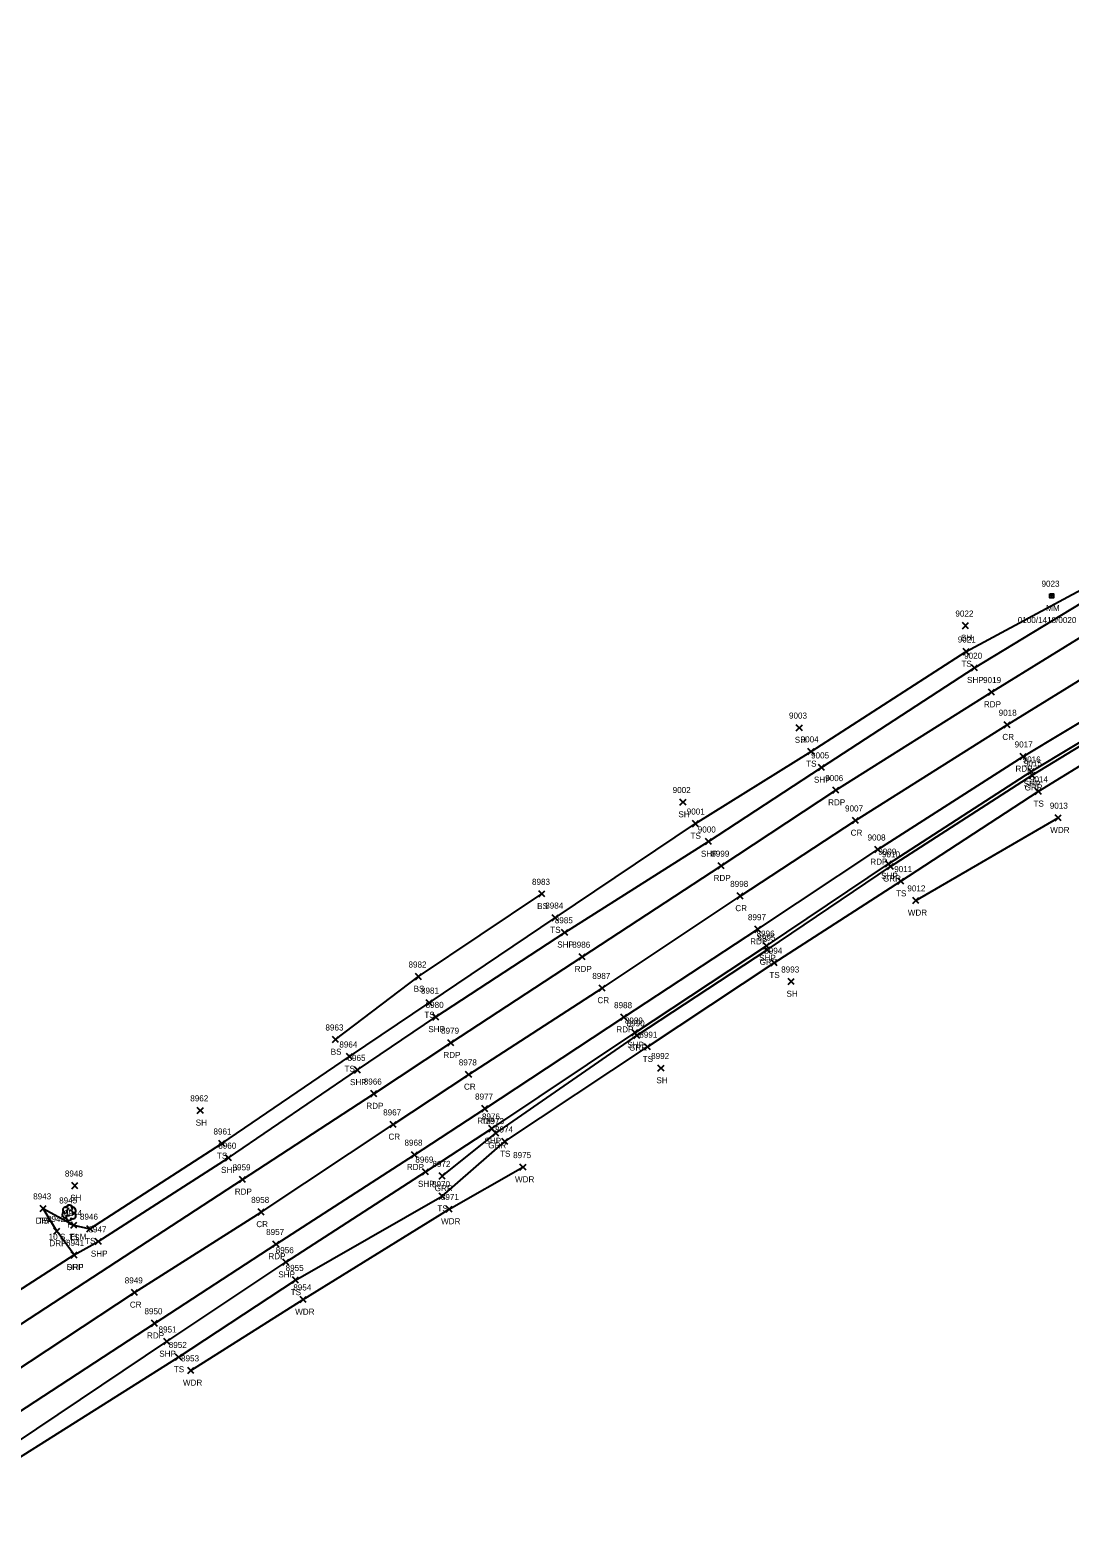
# Model space of a CAD drawing. Extents: x 1611797 to 1633212, y 298978 to 305475.
# Drawn here: x 1628602 to 1628945.1, y 304526.6 to 305024.4 of the extents above; entities that cross this region are included whole.
import ezdxf

# ---------------------------------------------------------------- set-up
doc = ezdxf.new("R2010")
doc.units = 0
for name, color, linetype in [('L_A', 7, 'Continuous'), ('L_C', 7, 'Continuous'), ('L_I', 7, 'Continuous'), ('L_TIC', 7, 'Continuous'), ('LAWA', 7, 'Continuous'), ('LELB', 7, 'Continuous'), ('LTD', 7, 'Continuous'), ('P_A', 7, 'Continuous'), ('P_I', 7, 'Continuous'), ('P_TIC', 7, 'Continuous'), ('PET', 7, 'Continuous'), ('PRC', 7, 'Continuous'), ('PSP', 7, 'Continuous'), ('R_A', 7, 'Continuous'), ('R_I', 7, 'Continuous'), ('R_TIC', 7, 'Continuous'), ('RDF', 7, 'Continuous'), ('RGR', 7, 'Continuous'), ('S_A', 7, 'Continuous'), ('S_C', 7, 'Continuous'), ('S_I', 7, 'Continuous'), ('SRM', 7, 'Continuous')]:
    doc.layers.add(name, color=color, linetype=linetype)

msp = doc.modelspace()

# ---------------------------------------------------------------- linework, layer by layer
at = {"layer": 'L_TIC'}
for points in [[(1628909.72, 304826.78), (1628911.72, 304828.78)], [(1628911.72, 304826.78), (1628909.72, 304828.78)], [(1628909.95, 304818.21), (1628911.95, 304820.21)], [(1628911.95, 304818.21), (1628909.95, 304820.21)], [(1628854.88, 304793.1), (1628856.88, 304795.1)], [(1628856.88, 304793.1), (1628854.88, 304795.1)], [(1628858.73, 304785.24), (1628860.73, 304787.24)], [(1628860.73, 304785.24), (1628858.73, 304787.24)], [(1628933.74, 304772.05), (1628935.74, 304774.05)], [(1628935.74, 304772.05), (1628933.74, 304774.05)], [(1628816.48, 304768.53), (1628818.48, 304770.53)], [(1628818.48, 304768.53), (1628816.48, 304770.53)], [(1628820.57, 304761.42), (1628822.57, 304763.42)], [(1628822.57, 304761.42), (1628820.57, 304763.42)], [(1628940.3, 304763.35), (1628942.3, 304765.35)], [(1628942.3, 304763.35), (1628940.3, 304765.35)], [(1628888.39, 304742.41), (1628890.39, 304744.41)], [(1628890.39, 304742.41), (1628888.39, 304744.41)], [(1628769.91, 304738.22), (1628771.91, 304740.22)], [(1628771.91, 304738.22), (1628769.91, 304740.22)], [(1628893.3, 304736.05), (1628895.3, 304738.05)], [(1628895.3, 304736.05), (1628893.3, 304738.05)], [(1628774.27, 304730.37), (1628776.27, 304732.37)], [(1628776.27, 304730.37), (1628774.27, 304732.37)], [(1628846.56, 304715.46), (1628848.56, 304717.46)], [(1628848.56, 304715.46), (1628846.56, 304717.46)], [(1628729.15, 304710.91), (1628731.15, 304712.91)], [(1628731.15, 304710.91), (1628729.15, 304712.91)], [(1628852.15, 304709.27), (1628854.15, 304711.27)], [(1628854.15, 304709.27), (1628852.15, 304711.27)], [(1628732.71, 304702.3), (1628734.71, 304704.3)], [(1628734.71, 304702.3), (1628732.71, 304704.3)], [(1628701.79, 304690.13), (1628703.79, 304692.13)], [(1628703.79, 304690.13), (1628701.79, 304692.13)], [(1628804.77, 304687.74), (1628806.77, 304689.74)], [(1628806.77, 304687.74), (1628804.77, 304689.74)], [(1628706.38, 304684.51), (1628708.38, 304686.51)], [(1628708.38, 304684.51), (1628706.38, 304686.51)], [(1628809.23, 304680.72), (1628811.23, 304682.72)], [(1628811.23, 304680.72), (1628809.23, 304682.72)], [(1628657.19, 304666.73), (1628659.19, 304668.73)], [(1628659.19, 304666.73), (1628657.19, 304668.73)], [(1628664.27, 304655.79), (1628666.27, 304657.79)], [(1628666.27, 304655.79), (1628664.27, 304657.79)], [(1628757.71, 304656.46), (1628759.71, 304658.46)], [(1628759.71, 304656.46), (1628757.71, 304658.46)], [(1628763.68, 304648), (1628765.68, 304650)], [(1628765.68, 304648), (1628763.68, 304650)], [(1628615.76, 304641.91), (1628617.76, 304643.91)], [(1628617.76, 304641.91), (1628615.76, 304643.91)], [(1628737.01, 304638.4), (1628739.01, 304640.4)], [(1628739.01, 304638.4), (1628737.01, 304640.4)], [(1628605.29, 304634.37), (1628607.29, 304636.37)], [(1628607.29, 304634.37), (1628605.29, 304636.37)], [(1628739.28, 304634.17), (1628741.28, 304636.17)], [(1628741.28, 304634.17), (1628739.28, 304636.17)], [(1628615.45, 304628.87), (1628617.45, 304630.87)], [(1628617.45, 304628.87), (1628615.45, 304630.87)], [(1628620.78, 304627.67), (1628622.78, 304629.67)], [(1628622.78, 304627.67), (1628620.78, 304629.67)], [(1628688.6, 304610.76), (1628690.6, 304612.76)], [(1628690.6, 304610.76), (1628688.6, 304612.76)], [(1628691.13, 304604.3), (1628693.13, 304606.3)], [(1628693.13, 304604.3), (1628691.13, 304606.3)], [(1628650.04, 304585.32), (1628652.04, 304587.32)], [(1628652.04, 304585.32), (1628650.04, 304587.32)], [(1628654.09, 304580.89), (1628656.09, 304582.89)], [(1628656.09, 304580.89), (1628654.09, 304582.89)]]:
    msp.add_lwpolyline(points, dxfattribs=at)
at = {"layer": 'LAWA'}
for points in [[(1628894.3, 304737.05), (1628941.3, 304764.35)], [(1628655.09, 304581.89), (1628692.13, 304605.3), (1628740.28, 304635.17), (1628764.68, 304649)]]:
    msp.add_lwpolyline(points, dxfattribs=at)
at = {"layer": 'LELB'}
for points in [[(1628606.29, 304635.37), (1628616.45, 304629.87), (1628621.78, 304628.67), (1628665.27, 304656.79), (1628707.38, 304685.51), (1628733.71, 304703.3), (1628775.27, 304731.37), (1628821.57, 304762.42), (1628859.73, 304786.24), (1628910.95, 304819.21), (1628950.46, 304840.54), (1628993.11, 304865.33), (1629005.75, 304871.93), (1629006.16, 304874.5), (1629003.64, 304877.43), (1628999.44, 304878.46)], [(1628556.42, 304526.63), (1628651.04, 304586.32), (1628689.6, 304611.76), (1628738.01, 304639.4), (1628758.71, 304657.46), (1628805.77, 304688.74), (1628847.56, 304716.46), (1628889.39, 304743.41), (1628934.74, 304773.05), (1628978.07, 304799.63)], [(1628702.79, 304691.13), (1628730.15, 304711.91), (1628770.91, 304739.22)]]:
    msp.add_lwpolyline(points, dxfattribs=at)
at = {"layer": 'LTD'}
msp.add_line((1628614.87, 304634.03), (1628614.87, 304634.03), dxfattribs=at)
msp.add_line((1628614.87, 304634.03), (1628614.87, 304634.03), dxfattribs=at)
msp.add_arc((1628614.92, 304635.47), 1.05, 335.5272, 180.9563, dxfattribs=at)
for centre, major_axis, ratio, start_param, end_param in [((1628613.79, 304633.32), (0.58, -1.04), 0.959034, 3.141593, 6.283185), ((1628614.08, 304634.7), (1.21, -0.51), 0.895232, 1.570796, 4.712389), ((1628614.41, 304633.28), (-0.625, -0.083), 0.423636, 0, 3.141593), ((1628614.66, 304634.49), (-0.208, -0.792), 0.645439, 3.141593, 6.283185), ((1628615.37, 304633.86), (-0.5, 0.667), 0.989748, 3.141593, 6.283185), ((1628615.87, 304633.2), (-1.09, 0.79), 0.841452, 1.570796, 4.712389), ((1628615.91, 304634.61), (-1.14, -0.48), 0.949671, 1.570796, 4.712389), ((1628614.87, 304632.53), (0.26, 1.06), 0.942809, 1.570796, 4.712389)]:
    msp.add_ellipse(centre, major_axis=major_axis, ratio=ratio, start_param=start_param, end_param=end_param, dxfattribs=at)
at = {"layer": 'P_TIC'}
for points in [[(1628912.68, 304812.87), (1628914.68, 304814.87)], [(1628914.68, 304812.87), (1628912.68, 304814.87)], [(1628918.29, 304804.83), (1628920.29, 304806.83)], [(1628920.29, 304804.83), (1628918.29, 304806.83)], [(1628923.43, 304794.06), (1628925.43, 304796.06)], [(1628925.43, 304794.06), (1628923.43, 304796.06)], [(1628928.7, 304783.57), (1628930.7, 304785.57)], [(1628930.7, 304783.57), (1628928.7, 304785.57)], [(1628862.16, 304779.95), (1628864.16, 304781.95)], [(1628864.16, 304779.95), (1628862.16, 304781.95)], [(1628931.4, 304778.61), (1628933.4, 304780.61)], [(1628933.4, 304778.61), (1628931.4, 304780.61)], [(1628866.88, 304772.46), (1628868.88, 304774.46)], [(1628868.88, 304772.46), (1628866.88, 304774.46)], [(1628873.38, 304762.44), (1628875.38, 304764.44)], [(1628875.38, 304762.44), (1628873.38, 304764.44)], [(1628824.86, 304755.49), (1628826.86, 304757.49)], [(1628826.86, 304755.49), (1628824.86, 304757.49)], [(1628880.81, 304752.85), (1628882.81, 304754.85)], [(1628882.81, 304752.85), (1628880.81, 304754.85)], [(1628829.09, 304747.51), (1628831.09, 304749.51)], [(1628831.09, 304747.51), (1628829.09, 304749.51)], [(1628884.34, 304748.19), (1628886.34, 304750.19)], [(1628886.34, 304748.19), (1628884.34, 304750.19)], [(1628835.32, 304737.53), (1628837.32, 304739.53)], [(1628837.32, 304737.53), (1628835.32, 304739.53)], [(1628777.44, 304725.52), (1628779.44, 304727.52)], [(1628779.44, 304725.52), (1628777.44, 304727.52)], [(1628841.16, 304726.54), (1628843.16, 304728.54)], [(1628843.16, 304726.54), (1628841.16, 304728.54)], [(1628844.08, 304721.12), (1628846.08, 304723.12)], [(1628846.08, 304721.12), (1628844.08, 304723.12)], [(1628783.24, 304717.47), (1628785.24, 304719.47)], [(1628785.24, 304717.47), (1628783.24, 304719.47)], [(1628789.81, 304707.15), (1628791.81, 304709.15)], [(1628791.81, 304707.15), (1628789.81, 304709.15)], [(1628734.89, 304697.59), (1628736.89, 304699.59)], [(1628736.89, 304697.59), (1628734.89, 304699.59)], [(1628796.99, 304697.5), (1628798.99, 304699.5)], [(1628798.99, 304697.5), (1628796.99, 304699.5)], [(1628800.57, 304692.41), (1628802.57, 304694.41)], [(1628802.57, 304692.41), (1628800.57, 304694.41)], [(1628739.91, 304689.07), (1628741.91, 304691.07)], [(1628741.91, 304689.07), (1628739.91, 304691.07)], [(1628709.07, 304680.1), (1628711.07, 304682.1)], [(1628711.07, 304680.1), (1628709.07, 304682.1)], [(1628745.76, 304678.6), (1628747.76, 304680.6)], [(1628747.76, 304678.6), (1628745.76, 304680.6)], [(1628714.49, 304672.27), (1628716.49, 304674.27)], [(1628716.49, 304672.27), (1628714.49, 304674.27)], [(1628751.12, 304667.32), (1628753.12, 304669.32)], [(1628753.12, 304667.32), (1628751.12, 304669.32)], [(1628720.83, 304662.09), (1628722.83, 304664.09)], [(1628722.83, 304662.09), (1628720.83, 304664.09)], [(1628753.44, 304660.73), (1628755.44, 304662.73)], [(1628755.44, 304660.73), (1628753.44, 304662.73)], [(1628666.51, 304651.12), (1628668.51, 304653.12)], [(1628668.51, 304651.12), (1628666.51, 304653.12)], [(1628727.87, 304652.1), (1628729.87, 304654.1)], [(1628729.87, 304652.1), (1628727.87, 304654.1)], [(1628731.48, 304646.51), (1628733.48, 304648.51)], [(1628733.48, 304646.51), (1628731.48, 304648.51)], [(1628671.08, 304643.96), (1628673.08, 304645.96)], [(1628673.08, 304643.96), (1628671.08, 304645.96)], [(1628677.24, 304633.21), (1628679.24, 304635.21)], [(1628679.24, 304633.21), (1628677.24, 304635.21)], [(1628623.53, 304623.47), (1628625.53, 304625.47)], [(1628625.53, 304623.47), (1628623.53, 304625.47)], [(1628682.17, 304622.61), (1628684.17, 304624.61)], [(1628684.17, 304622.61), (1628682.17, 304624.61)], [(1628615.57, 304619.02), (1628617.57, 304621.02)], [(1628617.57, 304619.02), (1628615.57, 304621.02)], [(1628685.39, 304616.61), (1628687.39, 304618.61)], [(1628687.39, 304616.61), (1628685.39, 304618.61)], [(1628635.51, 304606.63), (1628637.51, 304608.63)], [(1628637.51, 304606.63), (1628635.51, 304608.63)], [(1628642.11, 304596.45), (1628644.11, 304598.45)], [(1628644.11, 304596.45), (1628642.11, 304598.45)], [(1628646.11, 304590.43), (1628648.11, 304592.43)], [(1628648.11, 304590.43), (1628646.11, 304592.43)]]:
    msp.add_lwpolyline(points, dxfattribs=at)
at = {"layer": 'PET'}
for points in [[(1628539.34, 304558.37), (1628672.08, 304644.96), (1628715.49, 304673.27), (1628740.91, 304690.07), (1628784.24, 304718.47), (1628830.09, 304748.51), (1628867.88, 304773.46), (1628919.29, 304805.83), (1628957.78, 304829.65), (1629000.13, 304853.15), (1629018.89, 304863.53), (1629063.73, 304886), (1629107.94, 304906.85), (1629143.22, 304922.08), (1629185.06, 304938.86), (1629242.77, 304959.49), (1629284.03, 304972.45), (1629336.67, 304986.7), (1629382.46, 304997.36), (1629427.71, 305005.99), (1629469.83, 305012.59), (1629520.11, 305019.25), (1629549.49, 305022.22), (1629575.19, 305024.39)], [(1628549.92, 304536.59), (1628643.11, 304597.45), (1628683.17, 304623.61), (1628728.87, 304653.1), (1628752.12, 304668.32), (1628797.99, 304698.5), (1628842.16, 304727.54), (1628881.81, 304753.85), (1628929.7, 304784.57), (1628970.38, 304809.04)]]:
    msp.add_lwpolyline(points, dxfattribs=at)
at = {"layer": 'PRC'}
msp.add_lwpolyline([(1628544.35, 304546.87), (1628636.51, 304607.63), (1628678.24, 304634.21), (1628721.83, 304663.09), (1628746.76, 304679.6), (1628790.81, 304708.15), (1628836.32, 304738.53), (1628874.38, 304763.44), (1628924.43, 304795.06), (1628964.08, 304819.47)], dxfattribs=at)
at = {"layer": 'PSP'}
for points in [[(1628598, 304608.08), (1628616.57, 304620.02), (1628624.53, 304624.47), (1628667.51, 304652.12), (1628710.07, 304681.1), (1628735.89, 304698.59), (1628778.44, 304726.52), (1628825.86, 304756.49), (1628863.16, 304780.95), (1628913.68, 304813.87), (1628952.26, 304837.27)], [(1628554.23, 304529.06), (1628647.11, 304591.43), (1628686.39, 304617.61), (1628732.48, 304647.51), (1628754.44, 304661.73), (1628801.57, 304693.41), (1628845.08, 304722.12), (1628885.34, 304749.19), (1628932.4, 304779.61), (1628974.06, 304804.69)]]:
    msp.add_lwpolyline(points, dxfattribs=at)
at = {"layer": 'R_TIC'}
for points in [[(1628931.75, 304777.38), (1628933.75, 304779.38)], [(1628933.75, 304777.38), (1628931.75, 304779.38)], [(1628884.99, 304747.31), (1628886.99, 304749.31)], [(1628886.99, 304747.31), (1628884.99, 304749.31)], [(1628844.3, 304719.79), (1628846.3, 304721.79)], [(1628846.3, 304719.79), (1628844.3, 304721.79)], [(1628801.21, 304691.5), (1628803.21, 304693.5)], [(1628803.21, 304691.5), (1628801.21, 304693.5)], [(1628754.72, 304659.23), (1628756.72, 304661.23)], [(1628756.72, 304659.23), (1628754.72, 304661.23)], [(1628737.05, 304645.09), (1628739.05, 304647.09)], [(1628739.05, 304645.09), (1628737.05, 304647.09)], [(1628605.29, 304634.37), (1628607.29, 304636.37)], [(1628607.29, 304634.37), (1628605.29, 304636.37)], [(1628609.85, 304626.92), (1628611.85, 304628.92)], [(1628611.85, 304626.92), (1628609.85, 304628.92)], [(1628615.57, 304619.02), (1628617.57, 304621.02)], [(1628617.57, 304619.02), (1628615.57, 304621.02)]]:
    msp.add_lwpolyline(points, dxfattribs=at)
at = {"layer": 'RDF'}
msp.add_lwpolyline([(1628616.57, 304620.02), (1628610.85, 304627.92), (1628606.29, 304635.37)], dxfattribs=at)
at = {"layer": 'RGR'}
msp.add_lwpolyline([(1628738.05, 304646.09), (1628755.72, 304660.23), (1628802.21, 304692.5), (1628845.3, 304720.79), (1628885.99, 304748.31), (1628932.75, 304778.38), (1628974.37, 304803.82), (1629014.16, 304826.13), (1629034.21, 304836.96), (1629077.38, 304859.09), (1629118.22, 304878.1), (1629156.5, 304894.69), (1629196.83, 304909.84), (1629215.57, 304917.19), (1629227.63, 304919.91), (1629241.23, 304922.31)], dxfattribs=at)
at = {"layer": 'SRM'}
msp.add_lwpolyline([(1628938.52, 304838.27), (1628939.77, 304838.27), (1628939.77, 304837.02), (1628938.52, 304837.02)], close=True, dxfattribs=at)
msp.add_circle((1628939.14, 304837.64), 0.0833, dxfattribs=at)

# ---------------------------------------------------------------- texts
at = {"layer": 'L_A'}
for s, p in [('SH', (1628909.21, 304822.78)), ('TS', (1628909.36, 304814.21)), ('SH', (1628854.37, 304789.1)), ('TS', (1628858.14, 304781.24)), ('TS', (1628933.15, 304768.05)), ('SH', (1628815.97, 304764.53)), ('TS', (1628819.98, 304757.42)), ('WDR', (1628938.66, 304759.35)), ('TS', (1628887.8, 304738.41)), ('BS', (1628769.35, 304734.22)), ('WDR', (1628891.66, 304732.05)), ('TS', (1628773.68, 304726.37)), ('TS', (1628845.97, 304711.46)), ('BS', (1628728.59, 304706.91)), ('SH', (1628851.64, 304705.27)), ('TS', (1628732.12, 304698.3)), ('BS', (1628701.23, 304686.13)), ('TS', (1628804.18, 304683.74)), ('TS', (1628705.79, 304680.51)), ('SH', (1628808.71, 304676.72)), ('SH', (1628656.67, 304662.73)), ('TS', (1628663.68, 304651.79)), ('TS', (1628757.12, 304652.46)), ('WDR', (1628762.04, 304644)), ('SH', (1628615.25, 304637.91)), ('TS', (1628736.42, 304634.4)), ('TS', (1628604.7, 304630.37)), ('H', (1628614.3, 304629.03)), ('WDR', (1628737.64, 304630.17)), ('TS', (1628614.86, 304624.87)), ('TS', (1628620.19, 304623.67)), ('TS', (1628688.01, 304606.76)), ('WDR', (1628689.49, 304600.3)), ('TS', (1628649.45, 304581.32)), ('WDR', (1628652.45, 304576.89))]:
    msp.add_text(s, height=2, dxfattribs=at).set_placement(p)
at = {"layer": 'L_C'}
msp.add_text('10 S. ELM', height=2, dxfattribs=at).set_placement((1628608.13, 304625.03))
at = {"layer": 'L_I'}
for s, p in [('9022', (1628907.38, 304830.78)), ('9021', (1628908.17, 304822.21)), ('9003', (1628852.46, 304797.1)), ('9004', (1628856.31, 304789.24)), ('9014', (1628931.97, 304776.05)), ('9002', (1628814.07, 304772.53)), ('9001', (1628818.72, 304765.42)), ('9013', (1628938.53, 304767.35)), ('9011', (1628887.18, 304746.41)), ('8983', (1628767.65, 304742.22)), ('9012', (1628891.53, 304740.05)), ('8984', (1628772.02, 304734.37)), ('8994', (1628844.3, 304719.46)), ('8982', (1628726.89, 304714.91)), ('8993', (1628849.89, 304713.27)), ('8981', (1628731.01, 304706.3)), ('8963', (1628699.48, 304694.13)), ('8991', (1628803.08, 304691.74)), ('8964', (1628704.07, 304688.51)), ('8992', (1628806.97, 304684.72)), ('8962', (1628654.88, 304670.73)), ('8961', (1628662.53, 304659.79)), ('8974', (1628755.45, 304660.46)), ('8975', (1628761.42, 304652)), ('8948', (1628613.5, 304645.91)), ('8970', (1628734.66, 304642.4)), ('8943', (1628603.03, 304638.37)), ('8945', (1628611.61, 304637.03)), ('8971', (1628737.58, 304638.17)), ('8944', (1628613.19, 304632.87)), ('8946', (1628618.46, 304631.67)), ('8955', (1628686.34, 304614.76)), ('8954', (1628688.87, 304608.3)), ('8952', (1628647.78, 304589.32)), ('8953', (1628651.83, 304584.89))]:
    msp.add_text(s, height=2, dxfattribs=at).set_placement(p)
at = {"layer": 'P_A'}
for s, p in [('SHP', (1628911.22, 304808.87)), ('RDP', (1628916.78, 304800.83)), ('CR', (1628922.87, 304790.06)), ('SHP', (1628860.7, 304775.95)), ('RDP', (1628927.19, 304779.57)), ('SHP', (1628929.93, 304774.61)), ('RDP', (1628865.37, 304768.46)), ('CR', (1628872.81, 304758.44)), ('SHP', (1628823.4, 304751.49)), ('RDP', (1628879.3, 304748.85)), ('RDP', (1628827.58, 304743.51)), ('SHP', (1628882.88, 304744.19)), ('CR', (1628834.75, 304733.53)), ('SHP', (1628775.98, 304721.52)), ('RDP', (1628839.65, 304722.54)), ('SHP', (1628842.61, 304717.12)), ('RDP', (1628781.73, 304713.47)), ('CR', (1628789.24, 304703.15)), ('SHP', (1628733.43, 304693.59)), ('RDP', (1628795.48, 304693.5)), ('SHP', (1628799.11, 304688.41)), ('RDP', (1628738.4, 304685.07)), ('SHP', (1628707.6, 304676.1)), ('CR', (1628745.2, 304674.6)), ('RDP', (1628712.98, 304668.27)), ('RDP', (1628749.6, 304663.32)), ('CR', (1628720.27, 304658.09)), ('SHP', (1628751.98, 304656.73)), ('SHP', (1628665.05, 304647.12)), ('RDP', (1628726.36, 304648.1)), ('SHP', (1628730.02, 304642.51)), ('RDP', (1628669.57, 304639.96)), ('CR', (1628676.67, 304629.21)), ('SHP', (1628622.07, 304619.47)), ('RDP', (1628680.66, 304618.61)), ('SHP', (1628614.11, 304615.02)), ('SHP', (1628683.93, 304612.61)), ('CR', (1628634.94, 304602.63)), ('RDP', (1628640.6, 304592.45)), ('SHP', (1628644.64, 304586.43))]:
    msp.add_text(s, height=2, dxfattribs=at).set_placement(p)
at = {"layer": 'P_I'}
for s, p in [('9020', (1628910.26, 304816.87)), ('9019', (1628916.51, 304808.83)), ('9018', (1628921.66, 304798.06)), ('9017', (1628926.93, 304787.57)), ('9005', (1628859.75, 304783.95)), ('9016', (1628929.57, 304782.61)), ('9006', (1628864.4, 304776.46)), ('9007', (1628870.96, 304766.44)), ('9000', (1628822.36, 304759.49)), ('9008', (1628878.39, 304756.85)), ('8999', (1628826.82, 304751.51)), ('9009', (1628881.92, 304752.19)), ('8998', (1628833.06, 304741.53)), ('8997', (1628838.91, 304730.54)), ('8985', (1628775.18, 304729.52)), ('8986', (1628780.92, 304721.47)), ('8996', (1628841.76, 304725.12)), ('8987', (1628787.55, 304711.15)), ('8980', (1628732.54, 304701.59)), ('8988', (1628794.73, 304701.5)), ('8989', (1628798.3, 304696.41)), ('8979', (1628737.64, 304693.07)), ('8965', (1628706.76, 304684.1)), ('8978', (1628743.5, 304682.6)), ('8966', (1628712.13, 304676.27)), ('8977', (1628748.86, 304671.32)), ('8967', (1628718.53, 304666.09)), ('8976', (1628751.13, 304664.73)), ('8968', (1628725.57, 304656.1)), ('8960', (1628664.12, 304655.12)), ('8959', (1628668.82, 304647.96)), ('8969', (1628729.16, 304650.51)), ('8958', (1628674.98, 304637.21)), ('8947', (1628621.27, 304627.47)), ('8957', (1628679.91, 304626.61)), ('8941', (1628613.88, 304623.02)), ('8956', (1628683.08, 304620.61)), ('8949', (1628633.24, 304610.63)), ('8950', (1628639.76, 304600.45)), ('8951', (1628644.41, 304594.43))]:
    msp.add_text(s, height=2, dxfattribs=at).set_placement(p)
at = {"layer": 'R_A'}
for s, p in [('GRR', (1628930.23, 304773.38)), ('GRR', (1628883.48, 304743.31)), ('GRR', (1628842.79, 304715.79)), ('GRR', (1628799.7, 304687.5)), ('GRR', (1628753.21, 304655.23)), ('GRR', (1628735.54, 304641.09)), ('DRF', (1628603.83, 304630.37)), ('DRF', (1628608.39, 304622.92)), ('DRF', (1628614.11, 304615.02))]:
    msp.add_text(s, height=2, dxfattribs=at).set_placement(p)
at = {"layer": 'R_I'}
for s, p in [('9015', (1628929.97, 304781.38)), ('9010', (1628883.14, 304751.31)), ('8995', (1628842.04, 304723.79)), ('8990', (1628798.87, 304695.5)), ('8973', (1628752.46, 304663.23)), ('8972', (1628734.79, 304649.09)), ('8943', (1628603.03, 304638.37)), ('8942', (1628607.59, 304630.92)), ('8941', (1628613.88, 304623.02))]:
    msp.add_text(s, height=2, dxfattribs=at).set_placement(p)
at = {"layer": 'S_A'}
msp.add_text('MM', height=2, dxfattribs=at).set_placement((1628937.33, 304832.64))
at = {"layer": 'S_C'}
msp.add_text('0100/1418/0020', height=2, dxfattribs=at).set_placement((1628927.97, 304828.64))
at = {"layer": 'S_I'}
msp.add_text('9023', height=2, dxfattribs=at).set_placement((1628935.8, 304840.64))

doc.saveas('drawing.dxf')
